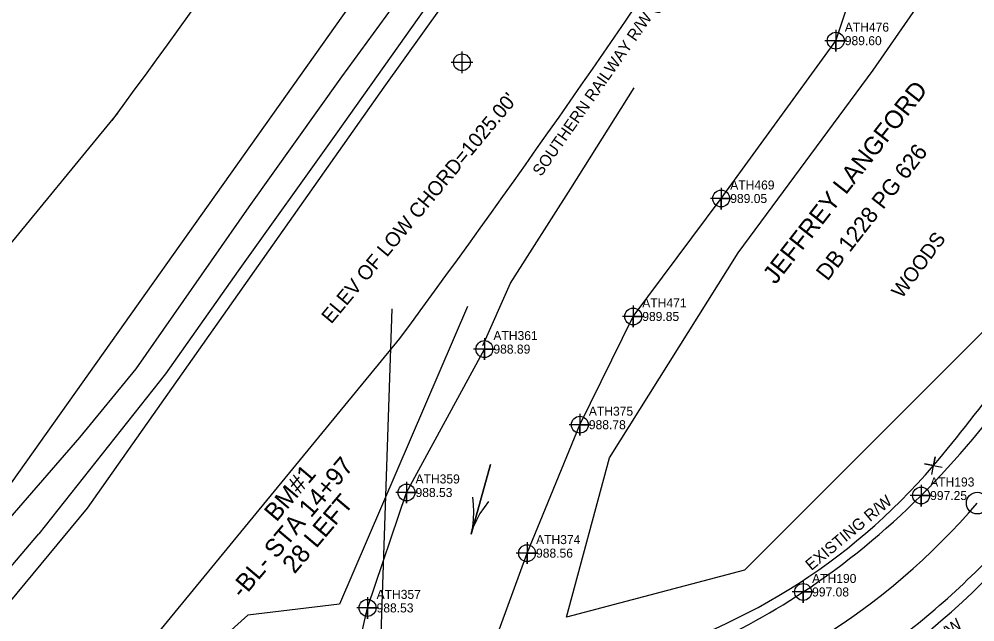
# Model space of a CAD drawing. Extents: x 1116345 to 1117546, y 660629 to 661859.
# Drawn here: x 1116970 to 1117234.8, y 661413.4 to 661580.4 of the extents above; entities that cross this region are included whole.
import ezdxf

# ---------------------------------------------------------------- set-up
doc = ezdxf.new("R2010")
doc.units = 0
for name, color, linetype in [('Cogo Default Point CELL', 7, 'Continuous'), ('CTL Sheet Text', 7, 'Continuous'), ('Exist DTM Drainline Cogo Elevation', 7, 'Continuous'), ('Exist DTM Drainline Cogo Number', 7, 'Continuous'), ('Exist DTM Drainline Cogo Point CELL', 7, 'Continuous'), ('Exist Horizontal Alignment', 7, 'Continuous'), ('Exist Horizontal Alignment Point', 7, 'Continuous'), ('Exist Hydro Jurisdictional Stream or Body of Water', 7, 'Continuous'), ('Exist Hydro River Flow Arrow CELL', 7, 'Continuous'), ('Exist Property Corner CELL', 7, 'Continuous'), ('Exist Property Deed Book Text', 7, 'Continuous'), ('Exist Property Owner Text', 7, 'Continuous'), ('Exist Right of Way Line', 7, 'Continuous'), ('Exist Right of Way Line Text', 7, 'Continuous'), ('Exist Roads EOP', 7, 'Continuous'), ('Exist Roads EOP Cogo Elevation', 7, 'Continuous'), ('Exist Roads EOP Cogo Number', 7, 'Continuous'), ('Exist Roads EOP Cogo Point CELL', 7, 'Continuous'), ('Exist Roads Soil', 7, 'Continuous'), ('Exist Utilities Power Pole Leader', 7, 'Continuous'), ('Exist Utilities Power Pole Text', 7, 'Continuous'), ('Exist Vegetation Woods Line', 7, 'Continuous'), ('Exist Vegetation Woods Line Text', 7, 'Continuous')]:
    doc.layers.add(name, color=color, linetype=linetype)

msp = doc.modelspace()

# ---------------------------------------------------------------- linework, layer by layer
at = {"layer": 'Cogo Default Point CELL'}
for points in [[(1117092.71, 661571.44), (1117092.71, 661568.44)], [(1117089.71, 661568.44), (1117092.71, 661568.44)], [(1117092.71, 661568.44), (1117095.71, 661568.44)], [(1117092.71, 661568.44), (1117092.71, 661565.44)]]:
    msp.add_lwpolyline(points, dxfattribs=at)
msp.add_circle((1117092.71, 661568.44), 2.34, dxfattribs=at)
at = {"layer": 'Exist DTM Drainline Cogo Point CELL'}
for points in [[(1117196.25, 661577.43), (1117196.25, 661571.43), (1117196.25, 661574.43), (1117199.25, 661574.43), (1117193.25, 661574.43)], [(1117164.52, 661533.7), (1117164.52, 661527.7), (1117164.52, 661530.7), (1117167.52, 661530.7), (1117161.52, 661530.7)], [(1117140.15, 661501.02), (1117140.15, 661495.02), (1117140.15, 661498.02), (1117143.15, 661498.02), (1117137.15, 661498.02)], [(1117098.92, 661491.98), (1117098.92, 661485.98), (1117098.92, 661488.98), (1117101.92, 661488.98), (1117095.92, 661488.98)], [(1117125.36, 661471.03), (1117125.36, 661465.03), (1117125.36, 661468.03), (1117128.36, 661468.03), (1117122.36, 661468.03)], [(1117077.35, 661452.25), (1117077.35, 661446.25), (1117077.35, 661449.25), (1117080.35, 661449.25), (1117074.35, 661449.25)], [(1117110.73, 661435.45), (1117110.73, 661429.45), (1117110.73, 661432.45), (1117113.73, 661432.45), (1117107.73, 661432.45)], [(1117066.56, 661420.27), (1117066.56, 661414.27), (1117066.56, 661417.27), (1117069.56, 661417.27), (1117063.56, 661417.27)]]:
    msp.add_lwpolyline(points, dxfattribs=at)
for centre in [(1117196.25, 661574.43), (1117164.52, 661530.7), (1117140.15, 661498.02), (1117098.92, 661488.98), (1117125.36, 661468.03), (1117077.35, 661449.25), (1117110.73, 661432.45), (1117066.56, 661417.27)]:
    msp.add_circle(centre, 2.34, dxfattribs=at)
at = {"layer": 'Exist Horizontal Alignment'}
msp.add_arc((1117092.71, 661568.44), 187.86, 284.1667, 319.4447, dxfattribs=at)
at = {"layer": 'Exist Horizontal Alignment Point'}
msp.add_line((1117233.16, 661448.25), (1117233.16, 661448.26), dxfattribs=at)
msp.add_circle((1117235.44, 661446.3), 3, dxfattribs=at)
at = {"layer": 'Exist Hydro Jurisdictional Stream or Body of Water'}
for points in [[(1117125.36, 661468.03), (1117140.15, 661498.02), (1117164.52, 661530.7), (1117196.25, 661574.43), (1117208.15, 661610.15), (1117250.57, 661671.87), (1117271.1, 661697.99)], [(1117098.47, 661489.98), (1117106.2, 661507.21), (1117122.91, 661533.45), (1117140.44, 661561.35)], [(1117058.44, 661381.41), (1117066.56, 661417.27), (1117077.35, 661449.25), (1117098.92, 661488.98)], [(1117095.99, 661391.98), (1117110.73, 661432.45), (1117125.36, 661468.03)]]:
    msp.add_lwpolyline(points, dxfattribs=at)
at = {"layer": 'Exist Hydro River Flow Arrow CELL'}
msp.add_line((1117097.9, 661447.34), (1117097.9, 661447.34), dxfattribs=at)
msp.add_lwpolyline([(1117100.1, 661446.73), (1117098.84, 661445.12), (1117097.7, 661443.39), (1117096.7, 661441.55), (1117095.85, 661439.66), (1117095.23, 661437.7), (1117100.57, 661456.98), (1117095.23, 661437.7), (1117095.7, 661439.7), (1117095.95, 661441.76), (1117096.04, 661443.85), (1117095.95, 661445.92), (1117095.69, 661447.95)], dxfattribs=at)
at = {"layer": 'Exist Property Corner CELL'}
msp.add_line((1117223.29, 661456.71), (1117223.29, 661456.71), dxfattribs=at)
msp.add_lwpolyline([(1117222.83, 661454.25), (1117223.75, 661459.16), (1117223.29, 661456.71), (1117220.83, 661457.17), (1117225.74, 661456.25)], dxfattribs=at)
at = {"layer": 'Exist Right of Way Line'}
for p, q in [((1116687.81, 661177.38), (1116997.4, 661554.39)), ((1116936.64, 661322.83), (1117075.51, 661491.94))]:
    msp.add_line(p, q, dxfattribs=at)
for centre, radius, start, end in [((1113861.12, 663924.32), 3869.72, 320.06667, 327.74218), ((1114555.87, 663349.35), 3030.27, 323.62772, 329.92248), ((1114555.87, 663349.35), 3130.27, 323.60349, 329.92248), ((1116945.23, 661694.65), 365.97, 319.4447, 329.4447), ((1117092.71, 661568.44), 171.86, 284.1667, 319.4447), ((1117092.71, 661568.44), 203.86, 284.1667, 319.4447)]:
    msp.add_arc(centre, radius, start, end, dxfattribs=at)
at = {"layer": 'Exist Roads EOP'}
for points in [[(1117102.29, 661387.33), (1117126.62, 661394.06), (1117156.42, 661404.98), (1117187.2, 661421.69), (1117219.89, 661448.41), (1117247.01, 661480.82), (1117275.55, 661531.18), (1117296.66, 661577.27), (1117320.8, 661635.68)], [(1117131.33, 661372.86), (1117166.32, 661382.85), (1117200.81, 661399.84), (1117238.07, 661430.32), (1117267.05, 661465.69), (1117295.47, 661519.13), (1117314.82, 661568.42)]]:
    msp.add_spline(points, degree=3, dxfattribs=at)
at = {"layer": 'Exist Roads EOP Cogo Point CELL'}
for points in [[(1117219.89, 661451.41), (1117219.89, 661445.41), (1117219.89, 661448.41), (1117222.89, 661448.41), (1117216.89, 661448.41)], [(1117187.2, 661424.69), (1117187.2, 661418.69), (1117187.2, 661421.69), (1117190.2, 661421.69), (1117184.2, 661421.69)]]:
    msp.add_lwpolyline(points, dxfattribs=at)
for centre in [(1117219.89, 661448.41), (1117187.2, 661421.69)]:
    msp.add_circle(centre, 2.34, dxfattribs=at)
at = {"layer": 'Exist Roads Soil'}
for points in [[(1116964.44, 661438.72), (1116986.86, 661464.48), (1117002.48, 661483.48), (1117033.75, 661528.36), (1117059.44, 661564.38), (1117076.95, 661588.51), (1117096.75, 661617.23), (1117115.73, 661643.92), (1117143.77, 661689), (1117184.56, 661750.96), (1117213.34, 661797.09), (1117219.45, 661808.47)], [(1117225.38, 661804.01), (1117219.15, 661793.59), (1117192.04, 661747.99), (1117171.01, 661715.33), (1117148.14, 661680), (1117113.02, 661627.81), (1117088.44, 661591.81), (1117057.75, 661548.54), (1117030.7, 661510.69), (1117010.61, 661482.09), (1116975.46, 661437.79)], [(1116733.8, 661143.62), (1116741.64, 661154.44), (1116759.33, 661176.15), (1116773.88, 661197.09), (1116797.54, 661224.23), (1116813.71, 661245.14), (1116851.6, 661289.9), (1116871.06, 661313.76), (1116898.57, 661347.77), (1116927.81, 661382.57), (1116965.68, 661426.24), (1116975.46, 661437.79)]]:
    msp.add_lwpolyline(points, dxfattribs=at)
at = {"layer": 'Exist Utilities Power Pole Leader'}
msp.add_line((1117069.35, 661381.02), (1117073.4, 661500.16), dxfattribs=at)
at = {"layer": 'Exist Vegetation Woods Line'}
for points in [[(1117208.66, 661815.33), (1117061.61, 661584.19), (1116958.01, 661438.28)], [(1116989.01, 661444.95), (1117071.18, 661561.57), (1117119.82, 661629.61), (1117196.26, 661744.55), (1117229.54, 661801.86)], [(1117331.77, 661706.88), (1117284.76, 661578.38), (1117241.02, 661497.84), (1117170.97, 661427.76), (1117121.7, 661414.67), (1117133.58, 661458.9), (1117169.21, 661515.67), (1117206.6, 661566.28), (1117265.11, 661650.77), (1117285.78, 661686.42), (1117290.62, 661714.15)], [(1117094.23, 661500.8), (1117058.79, 661418.32), (1117033.4, 661415.3), (1117015.05, 661398.7), (1116992.26, 661393.47)], [(1116740.57, 661137.11), (1116758.17, 661158.85), (1116797.8, 661207.69), (1116868.5, 661301.41), (1116920.29, 661361.98), (1116989.01, 661444.95)]]:
    msp.add_lwpolyline(points, dxfattribs=at)

# ---------------------------------------------------------------- texts
at = {"layer": 'CTL Sheet Text'}
for s, p in [('-BL- STA 14+97', (1117031.93, 661419.62)), ('BM#1', (1117041.32, 661440.9)), ('28 LEFT', (1117046.32, 661426.48))]:
    msp.add_text(s, height=5, rotation=49.8065, dxfattribs=at).set_placement(p)
at = {"layer": 'Exist DTM Drainline Cogo Elevation'}
for s, p in [('989.60', (1117198.75, 661573.18)), ('989.05', (1117167.02, 661529.45)), ('989.85', (1117142.65, 661496.77)), ('988.89', (1117101.42, 661487.73)), ('988.78', (1117127.86, 661466.78)), ('988.53', (1117079.85, 661448)), ('988.56', (1117113.23, 661431.2)), ('988.53', (1117069.06, 661416.02))]:
    msp.add_text(s, height=2.5, dxfattribs=at).set_placement(p)
at = {"layer": 'Exist DTM Drainline Cogo Number'}
for s, p in [('ATH476', (1117198.75, 661576.93)), ('ATH469', (1117167.02, 661533.2)), ('ATH471', (1117142.65, 661500.52)), ('ATH361', (1117101.42, 661491.48)), ('ATH375', (1117127.86, 661470.53)), ('ATH359', (1117079.85, 661451.75)), ('ATH374', (1117113.23, 661434.95)), ('ATH357', (1117069.06, 661419.77))]:
    msp.add_text(s, height=2.5, dxfattribs=at).set_placement(p)
at = {"layer": 'Exist Property Deed Book Text'}
msp.add_text('DB 1228 PG 626', height=4.5, rotation=52.1366, dxfattribs=at).set_placement((1117193.97, 661507.64))
at = {"layer": 'Exist Property Owner Text'}
msp.add_text('JEFFREY LANGFORD', height=5, rotation=51.9041, dxfattribs=at).set_placement((1117179.54, 661506.68))
at = {"layer": 'Exist Right of Way Line Text'}
for s, rotation, p in [('SOUTHERN RAILWAY R/W (RAILROAD ABANDONED)', 55.0555, (1117114.63, 661536.62)), ('EXISTING R/W', 39.8049, (1117189.49, 661427.47)), ('EXISTING R/W', 37.8811, (1117208.29, 661393.99))]:
    msp.add_text(s, height=3.2, rotation=rotation, dxfattribs=at).set_placement(p)
at = {"layer": 'Exist Roads EOP Cogo Elevation'}
for s, p in [('997.25', (1117222.39, 661447.16)), ('997.08', (1117189.7, 661420.44))]:
    msp.add_text(s, height=2.5, dxfattribs=at).set_placement(p)
at = {"layer": 'Exist Roads EOP Cogo Number'}
for s, p in [('ATH193', (1117222.39, 661450.91)), ('ATH190', (1117189.7, 661424.19))]:
    msp.add_text(s, height=2.5, dxfattribs=at).set_placement(p)
at = {"layer": 'Exist Utilities Power Pole Text'}
msp.add_text("ELEV OF LOW CHORD=1025.00'", height=4, rotation=50.2307, dxfattribs=at).set_placement((1117056.5, 661495.76))
at = {"layer": 'Exist Vegetation Woods Line Text'}
msp.add_text('WOODS', height=4, rotation=53.6027, dxfattribs=at).set_placement((1117214.55, 661502.78))

doc.saveas('drawing.dxf')
